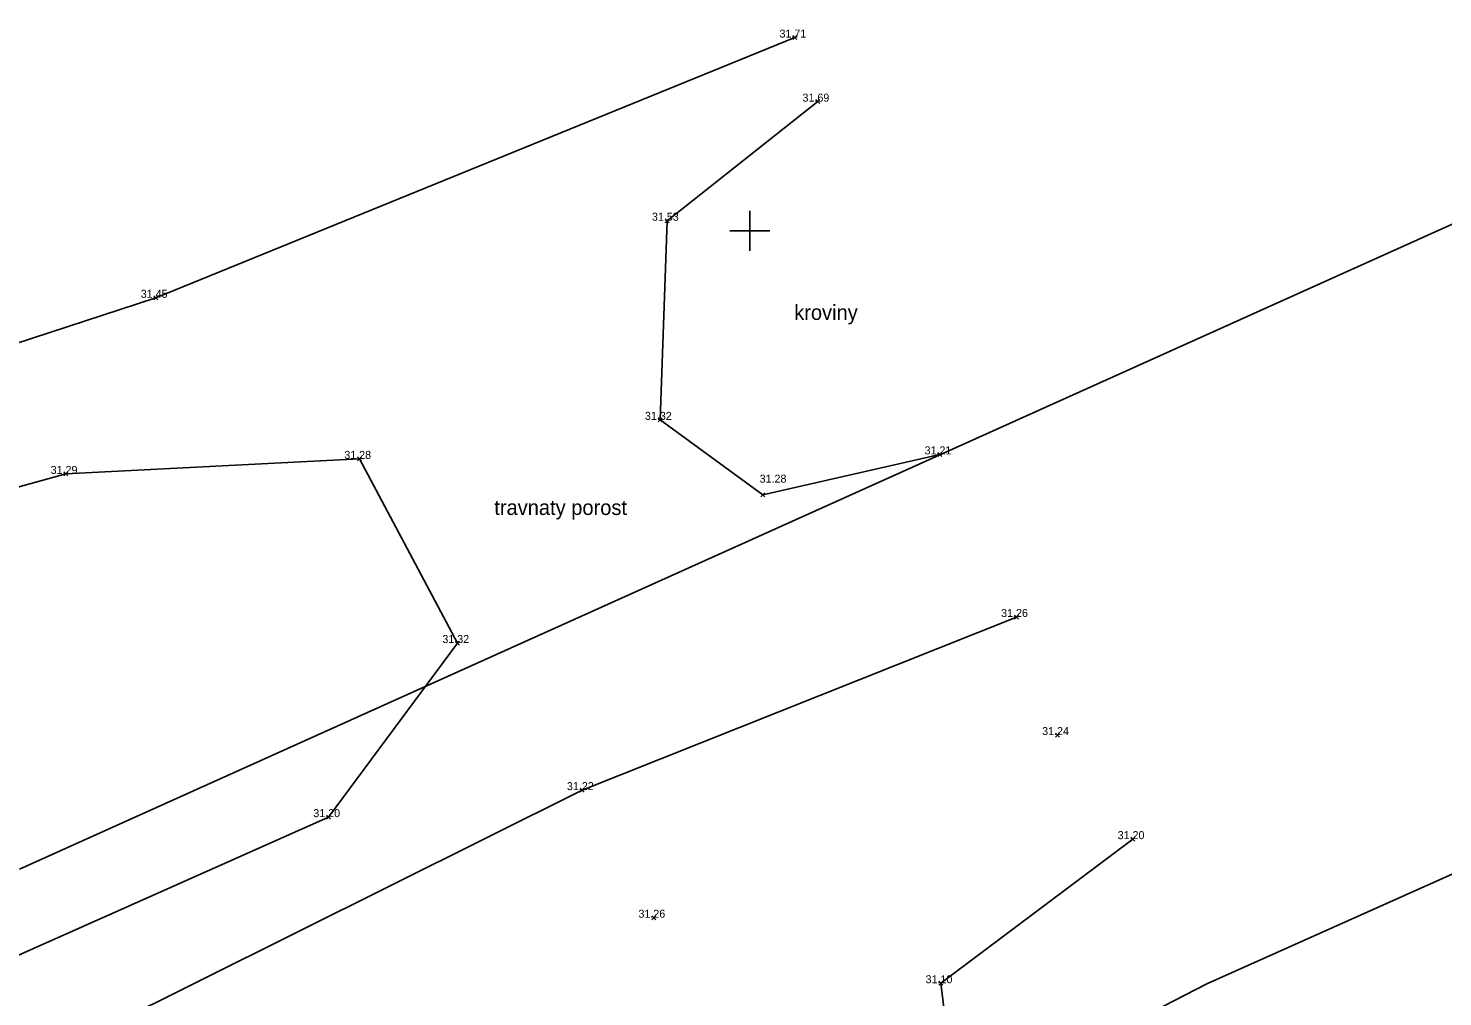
# Model space of a CAD drawing. Extents: x -772865 to -772533, y -1034366 to -1034132.
# Drawn here: x -772589.42 to -772561.15, y -1034215.31 to -1034195.95 of the extents above; entities that cross this region are included whole.
import ezdxf

# ---------------------------------------------------------------- set-up
doc = ezdxf.new("R2010")
doc.units = 0
for name, color, linetype in [('body', 7, 'Continuous'), ('KM_hranice', 7, 'Continuous'), ('mistni_popis', 7, 'Continuous'), ('oddeleni_ploch', 7, 'Continuous'), ('souradnicova_sit', 7, 'Continuous'), ('stromy_kere', 7, 'Continuous'), ('vyskove_koty', 7, 'Continuous')]:
    doc.layers.add(name, color=color, linetype=linetype)

msp = doc.modelspace()

# ---------------------------------------------------------------- linework, layer by layer
at = {"layer": 'body'}
for p, q in [((-772574.06, -1034196.18), (-772574.14, -1034196.1)), ((-772574.14, -1034196.18), (-772574.06, -1034196.1)), ((-772573.6, -1034197.46), (-772573.68, -1034197.38)), ((-772573.68, -1034197.46), (-772573.6, -1034197.38)), ((-772576.61, -1034199.84), (-772576.69, -1034199.76)), ((-772576.69, -1034199.84), (-772576.61, -1034199.76)), ((-772586.83, -1034201.38), (-772586.91, -1034201.3)), ((-772586.91, -1034201.38), (-772586.83, -1034201.3)), ((-772576.75, -1034203.82), (-772576.83, -1034203.74)), ((-772576.83, -1034203.82), (-772576.75, -1034203.74)), ((-772582.76, -1034204.6), (-772582.84, -1034204.52)), ((-772582.84, -1034204.6), (-772582.76, -1034204.52)), ((-772571.16, -1034204.51), (-772571.24, -1034204.43)), ((-772571.24, -1034204.51), (-772571.16, -1034204.43)), ((-772588.63, -1034204.9), (-772588.71, -1034204.82)), ((-772588.71, -1034204.9), (-772588.63, -1034204.82)), ((-772574.7, -1034205.32), (-772574.78, -1034205.24)), ((-772574.78, -1034205.32), (-772574.7, -1034205.24)), ((-772569.63, -1034207.76), (-772569.71, -1034207.68)), ((-772569.71, -1034207.76), (-772569.63, -1034207.68)), ((-772580.8, -1034208.28), (-772580.88, -1034208.2)), ((-772580.88, -1034208.28), (-772580.8, -1034208.2)), ((-772568.81, -1034210.12), (-772568.89, -1034210.04)), ((-772568.89, -1034210.12), (-772568.81, -1034210.04)), ((-772578.31, -1034211.22), (-772578.39, -1034211.14)), ((-772578.39, -1034211.22), (-772578.31, -1034211.14)), ((-772583.38, -1034211.76), (-772583.46, -1034211.68)), ((-772583.46, -1034211.76), (-772583.38, -1034211.68)), ((-772567.3, -1034212.2), (-772567.38, -1034212.12)), ((-772567.38, -1034212.2), (-772567.3, -1034212.12)), ((-772576.88, -1034213.77), (-772576.96, -1034213.69)), ((-772576.96, -1034213.77), (-772576.88, -1034213.69)), ((-772571.14, -1034215.08), (-772571.22, -1034215)), ((-772571.22, -1034215.08), (-772571.14, -1034215))]:
    msp.add_line(p, q, dxfattribs=at)
at = {"layer": 'KM_hranice'}
for p, q in [((-772549.99, -1034194.93), (-772589.6, -1034212.76)), ((-772532.872, -1034200.309), (-772565.86, -1034215.05)), ((-772565.86, -1034215.05), (-772568.1, -1034216.2))]:
    msp.add_line(p, q, dxfattribs=at)
at = {"layer": 'oddeleni_ploch'}
for points in [[(-772574.1, -1034196.14), (-772586.87, -1034201.34), (-772598.23, -1034205.06), (-772614.53, -1034207.42), (-772626.93, -1034206.95), (-772636.66, -1034207.26), (-772647.96, -1034208.36), (-772659.39, -1034213.08), (-772672.58, -1034218.62), (-772687.49, -1034225.14), (-772703.01, -1034232.02), (-772714.35, -1034236.9), (-772728.88, -1034243.07), (-772737.97, -1034245.74), (-772746.8, -1034246.99), (-772753.85, -1034250.11), (-772762.71, -1034257.3), (-772782.05, -1034269.18), (-772797.09, -1034276.39), (-772810.61, -1034282.39), (-772816.13, -1034284.08), (-772822.76, -1034283.4), (-772826.73, -1034280.27)], [(-772569.67, -1034207.72), (-772578.35, -1034211.18), (-772588.33, -1034216.15), (-772592.11, -1034217.46), (-772598.89, -1034219.1), (-772610.21, -1034219.57), (-772621.14, -1034219.48), (-772637.34, -1034221.06), (-772647.54, -1034222.08), (-772674.34, -1034233.24), (-772685.01, -1034239.21), (-772697.33, -1034242.95), (-772712.12, -1034249.56), (-772725.85, -1034254.8), (-772738.85, -1034261.98), (-772750.37, -1034267.76), (-772764, -1034272.65), (-772783.9, -1034280.59), (-772796.38, -1034286.28), (-772810.31, -1034291.67), (-772823.61, -1034294.35), (-772828.52, -1034296.12), (-772827.01, -1034302.81), (-772823.23, -1034300.75)], [(-772567.34, -1034212.16), (-772571.18, -1034215.04), (-772571.09, -1034215.8), (-772573.98, -1034216.98), (-772577.45, -1034219.11), (-772584.7, -1034223.05), (-772595.02, -1034228.2), (-772607.45, -1034233.93), (-772615.83, -1034237.74), (-772627.86, -1034242.86), (-772647.89, -1034252.03), (-772658, -1034256.56), (-772672.84, -1034263.1), (-772676.49, -1034257.87), (-772679.65, -1034256.43), (-772682.64, -1034256.79), (-772689.63, -1034259.88), (-772704.53, -1034266.45)]]:
    msp.add_lwpolyline(points, dxfattribs=at)
at = {"layer": 'souradnicova_sit'}
for p, q in [((-772575, -1034199.6), (-772575, -1034200.4)), ((-772575.4, -1034200), (-772574.6, -1034200))]:
    msp.add_line(p, q, dxfattribs=at)
at = {"layer": 'stromy_kere'}
for points in [[(-772571.2, -1034204.47), (-772574.74, -1034205.28), (-772576.79, -1034203.78), (-772576.65, -1034199.8), (-772573.64, -1034197.42)], [(-772593.5, -1034206.2), (-772588.67, -1034204.86), (-772582.8, -1034204.56), (-772580.84, -1034208.24), (-772583.42, -1034211.72), (-772590.3, -1034214.78)]]:
    msp.add_lwpolyline(points, dxfattribs=at)

# ---------------------------------------------------------------- texts
at = {"layer": 'mistni_popis'}
for s, p in [('kroviny', (-772574.112, -1034201.782)), ('travnaty porost', (-772580.107, -1034205.681))]:
    msp.add_text(s, height=0.3, dxfattribs=at).set_placement(p)
at = {"layer": 'vyskove_koty'}
for s, p in [('31.71', (-772574.405, -1034196.14)), ('31.69', (-772573.945, -1034197.42)), ('31.53', (-772576.955, -1034199.8)), ('31.45', (-772587.175, -1034201.34)), ('31.32', (-772577.095, -1034203.78)), ('31.21', (-772571.505, -1034204.47)), ('31.28', (-772583.105, -1034204.56)), ('31.29', (-772588.975, -1034204.86)), ('31.28', (-772574.802, -1034205.035)), ('31.26', (-772569.975, -1034207.72)), ('31.32', (-772581.145, -1034208.24)), ('31.24', (-772569.155, -1034210.08)), ('31.22', (-772578.655, -1034211.18)), ('31.20', (-772583.725, -1034211.72)), ('31.20', (-772567.645, -1034212.16)), ('31.26', (-772577.225, -1034213.73)), ('31.10', (-772571.485, -1034215.04))]:
    msp.add_text(s, height=0.16, dxfattribs=at).set_placement(p)

doc.saveas('drawing.dxf')
